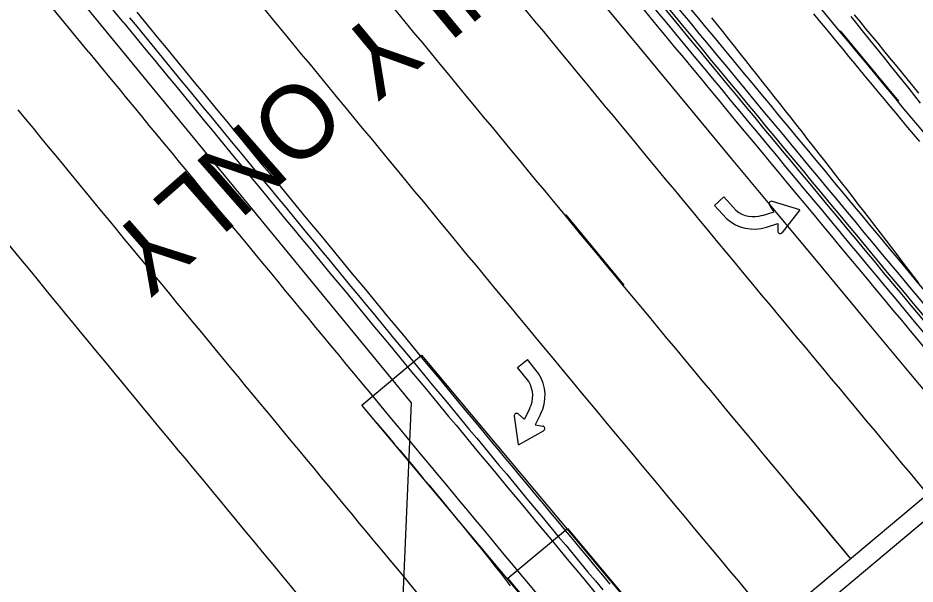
# Model space of a CAD drawing. Extents: x 2252205 to 2259955, y 13788514 to 13798103.
# Drawn here: x 2256222.6 to 2256320.8, y 13792305 to 13792366.9 of the extents above; entities that cross this region are included whole.
import ezdxf

# ---------------------------------------------------------------- set-up
doc = ezdxf.new("R2010")
doc.units = 0
for name, color, linetype in [('D_RDWY_TRACK_BUS', 7, 'Continuous'), ('D_RDWY_TRACK_TRUCK_WB62', 7, 'Continuous'), ('GEOM_CENTERLINE_ALIGN', 7, 'Continuous'), ('ROAD_BIKE_SHARED_USE', 7, 'Continuous'), ('Road_Curb_Back', 7, 'Continuous'), ('Road_Curb_Face', 7, 'Continuous'), ('Road_EdgeOfPavementInside', 7, 'Continuous'), ('Road_EdgeOfPavementOutside', 7, 'Continuous'), ('ROAD_ROW_EXIST', 7, 'Continuous'), ('ROAD_ROW_PROPOSED', 7, 'Continuous'), ('TRAF_PAVMRK_W_24IN_SLD', 7, 'Continuous'), ('TRAF_PAVMRK_W_4IN_BRK', 7, 'Continuous'), ('TRAF_PAVMRK_W_4IN_SLD', 7, 'Continuous'), ('TRAF_PAVMRK_W_8IN_SLD', 7, 'Continuous'), ('TRAF_PAVMRK_W_LT_TRN_ARROW_WORD', 7, 'Continuous'), ('TRAF_PAVMRK_W_RT_TRN_ARROW_WORD', 7, 'Continuous'), ('TRAF_PAVMRK_Y_4IN_SLD', 7, 'Continuous')]:
    doc.layers.add(name, color=color, linetype=linetype)

msp = doc.modelspace()

# ---------------------------------------------------------------- linework, layer by layer
at = {"layer": 'D_RDWY_TRACK_BUS'}
for points in [[(2256321.301, 13792353.365), (2256320.652, 13792354.142), (2256320.003, 13792354.919), (2256319.355, 13792355.695), (2256318.708, 13792356.472), (2256318.062, 13792357.249), (2256317.416, 13792358.026), (2256316.77, 13792358.802), (2256316.125, 13792359.579), (2256315.481, 13792360.356), (2256314.837, 13792361.132), (2256314.194, 13792361.909), (2256313.552, 13792362.686), (2256312.909, 13792363.462), (2256312.268, 13792364.239), (2256311.626, 13792365.015), (2256310.986, 13792365.792), (2256310.345, 13792366.569), (2256309.705, 13792367.345)], [(2256321.403, 13792357.579), (2256320.768, 13792358.373), (2256320.133, 13792359.165), (2256319.498, 13792359.958), (2256318.863, 13792360.749), (2256318.227, 13792361.539), (2256317.592, 13792362.329), (2256316.957, 13792363.118), (2256316.321, 13792363.906), (2256315.686, 13792364.693), (2256315.05, 13792365.48), (2256314.414, 13792366.266), (2256313.779, 13792367.051)], [(2256321.231, 13792337.838), (2256320.631, 13792338.631), (2256320.03, 13792339.423), (2256319.429, 13792340.215), (2256318.826, 13792341.007), (2256318.222, 13792341.797), (2256317.617, 13792342.588), (2256317.011, 13792343.378), (2256316.405, 13792344.167), (2256315.797, 13792344.956), (2256315.189, 13792345.745), (2256314.58, 13792346.533), (2256313.97, 13792347.32), (2256313.359, 13792348.108), (2256312.748, 13792348.895), (2256312.136, 13792349.681), (2256311.523, 13792350.468), (2256310.91, 13792351.254), (2256310.296, 13792352.039), (2256309.681, 13792352.824), (2256309.066, 13792353.609), (2256308.451, 13792354.394), (2256307.834, 13792355.178), (2256307.218, 13792355.963), (2256306.601, 13792356.746), (2256305.983, 13792357.53), (2256305.365, 13792358.313), (2256304.746, 13792359.096), (2256304.127, 13792359.879), (2256303.508, 13792360.662), (2256302.888, 13792361.444), (2256302.268, 13792362.227), (2256301.648, 13792363.009), (2256301.027, 13792363.791), (2256300.406, 13792364.572), (2256299.785, 13792365.354), (2256299.163, 13792366.135), (2256298.541, 13792366.916)], [(2256307.791, 13792281.165), (2256311.646, 13792276.566), (2256305.131, 13792271.106), (2256276.224, 13792305.593), (2256282.738, 13792311.054), (2256307.791, 13792281.165)]]:
    msp.add_lwpolyline(points, dxfattribs=at)
at = {"layer": 'D_RDWY_TRACK_TRUCK_WB62'}
for points in [[(2256321.207, 13792358.664), (2256320.568, 13792359.445), (2256319.929, 13792360.225), (2256319.29, 13792361.005), (2256318.651, 13792361.785), (2256318.012, 13792362.564), (2256317.373, 13792363.342), (2256316.735, 13792364.121), (2256316.096, 13792364.898), (2256315.457, 13792365.676), (2256314.818, 13792366.453), (2256314.179, 13792367.229)], [(2256308.191, 13792280.564), (2256310.761, 13792277.498), (2256304.248, 13792272.037), (2256260.237, 13792324.528), (2256266.75, 13792329.989), (2256308.191, 13792280.564)], [(2256261.843, 13792322.612), (2256262.485, 13792321.846), (2256263.127, 13792321.08), (2256263.768, 13792320.315), (2256264.408, 13792319.552), (2256265.047, 13792318.79), (2256265.683, 13792318.03), (2256266.317, 13792317.272), (2256266.948, 13792316.516), (2256267.577, 13792315.763), (2256268.202, 13792315.012), (2256268.824, 13792314.264), (2256269.442, 13792313.518), (2256270.056, 13792312.775), (2256270.666, 13792312.034), (2256271.271, 13792311.297), (2256271.871, 13792310.561), (2256272.466, 13792309.829), (2256273.056, 13792309.099), (2256273.641, 13792308.371), (2256274.219, 13792307.647), (2256274.792, 13792306.924), (2256275.358, 13792306.205), (2256275.918, 13792305.487), (2256276.472, 13792304.772)]]:
    msp.add_lwpolyline(points, dxfattribs=at)
at = {"layer": 'GEOM_CENTERLINE_ALIGN'}
msp.add_arc((2265118.999, 13799669.27), 11459.16, 219.4185534, 224.3273853, dxfattribs=at)
at = {"layer": 'ROAD_BIKE_SHARED_USE'}
msp.add_line((2256230.297, 13792363.186), (2256103.519, 13792517.426), dxfattribs=at)
for radius, end in [(11505.993, 219.8337025), (11515.993, 219.8337803)]:
    msp.add_arc((2265118.999, 13799669.27), radius, 219.4185534, end, dxfattribs=at)
at = {"layer": 'Road_Curb_Back'}
msp.add_line((2256234.159, 13792366.361), (2256107.555, 13792520.389), dxfattribs=at)
for radius, end in [(11454.327, 219.921869), (11453.993, 219.921869), (11500.993, 219.8232636)]:
    msp.add_arc((2265118.999, 13799669.27), radius, 219.4185534, end, dxfattribs=at)
at = {"layer": 'Road_Curb_Face'}
msp.add_arc((2265118.999, 13799669.27), 11500.16, 219.4185534, 219.8232636, dxfattribs=at)
at = {"layer": 'Road_EdgeOfPavementInside'}
for radius in [11453.16, 11455.16]:
    msp.add_arc((2265118.999, 13799669.27), radius, 219.4185534, 219.921869, dxfattribs=at)
at = {"layer": 'Road_EdgeOfPavementOutside'}
msp.add_arc((2265118.999, 13799669.27), 11500.16, 219.4185534, 219.8232636, dxfattribs=at)
at = {"layer": 'ROAD_ROW_EXIST'}
for p, q in [((2256265.673, 13792324.773), (2256010.405, 13792635.338)), ((2256260.792, 13792213.5), (2256265.673, 13792324.773))]:
    msp.add_line(p, q, dxfattribs=at)
at = {"layer": 'ROAD_ROW_PROPOSED'}
msp.add_arc((2265116.017, 13799666.597), 11522.16, 219.4185534, 219.8015342, dxfattribs=at)
at = {"layer": 'TRAF_PAVMRK_W_24IN_SLD'}
for p, q in [((2256329.829, 13792321.201), (2256295.321, 13792292.32)), ((2256296.15, 13792290.406), (2256331.113, 13792319.667))]:
    msp.add_line(p, q, dxfattribs=at)
at = {"layer": 'TRAF_PAVMRK_W_4IN_BRK'}
for points in [[(2256319, 13792357.789), (2256312.616, 13792365.486)], [(2256319.006, 13792357.781), (2256319, 13792357.789)], [(2256282.535, 13792345.348), (2256282.542, 13792345.341)], [(2256282.542, 13792345.341), (2256288.924, 13792337.642)], [(2256308.07, 13792314.546), (2256308.076, 13792314.538)], [(2256308.076, 13792314.538), (2256313.725, 13792307.723)]]:
    msp.add_lwpolyline(points, dxfattribs=at)
for radius, end in [(11441.16, 219.921869), (11477.16, 219.8969182)]:
    msp.add_arc((2265118.999, 13799669.27), radius, 219.4185534, end, dxfattribs=at)
at = {"layer": 'TRAF_PAVMRK_W_4IN_SLD'}
msp.add_arc((2265118.999, 13799669.27), 11499.16, 219.4185534, 219.8232636, dxfattribs=at)
at = {"layer": 'TRAF_PAVMRK_W_8IN_SLD'}
for radius, end in [(11466.16, 219.8968895), (11488.16, 219.8969469)]:
    msp.add_arc((2265118.999, 13799669.27), radius, 219.4185534, end, dxfattribs=at)
at = {"layer": 'TRAF_PAVMRK_W_LT_TRN_ARROW_WORD'}
for p, q in [((2256299.859, 13792347.318), (2256298.834, 13792346.379)), ((2256300.152, 13792344.94), (2256298.834, 13792346.379)), ((2256301.175, 13792345.852), (2256299.859, 13792347.318)), ((2256299.859, 13792347.318), (2256299.859, 13792347.318)), ((2256305.342, 13792345.711), (2256304.879, 13792346.394)), ((2256308.179, 13792345.882), (2256305.181, 13792346.809)), ((2256304.081, 13792345.28), (2256305.362, 13792345.688)), ((2256308.193, 13792345.881), (2256306.237, 13792343.413)), ((2256304.511, 13792344.004), (2256305.756, 13792344.409)), ((2256305.756, 13792344.409), (2256305.761, 13792343.571))]:
    msp.add_line(p, q, dxfattribs=at)
for centre, radius, start, end in [((2256305.095, 13792346.561), 0.274, 72.80028, 215.06335), ((2256303.131, 13792348.207), 3.06, 230.36726, 288.14805), ((2256303.131, 13792348.207), 4.419, 227.61601, 288.19323), ((2256306.026, 13792343.576), 0.274, 179.73814, 322.00121)]:
    msp.add_arc(centre, radius, start, end, dxfattribs=at)
at = {"layer": 'TRAF_PAVMRK_W_RT_TRN_ARROW_WORD'}
for p, q in [((2256277.264, 13792328.651), (2256278.354, 13792329.514)), ((2256279.566, 13792327.985), (2256278.354, 13792329.514)), ((2256278.504, 13792327.119), (2256277.264, 13792328.651)), ((2256277.264, 13792328.651), (2256277.264, 13792328.651)), ((2256278.609, 13792324.16), (2256278.003, 13792322.96)), ((2256277.365, 13792320.208), (2256276.924, 13792323.315)), ((2256277.983, 13792322.982), (2256277.383, 13792323.548)), ((2256279.8, 13792323.533), (2256279.204, 13792322.367)), ((2256279.204, 13792322.367), (2256280.03, 13792322.231)), ((2256277.364, 13792320.194), (2256280.111, 13792321.735))]:
    msp.add_line(p, q, dxfattribs=at)
for centre, radius, start, end in [((2256275.868, 13792325.56), 4.419, 332.70299, 33.28021), ((2256275.868, 13792325.56), 3.06, 332.74817, 30.52896), ((2256277.184, 13792323.361), 0.274, 45.83287, 188.09595), ((2256279.983, 13792321.97), 0.274, 298.89501, 81.15808)]:
    msp.add_arc(centre, radius, start, end, dxfattribs=at)
at = {"layer": 'TRAF_PAVMRK_Y_4IN_SLD'}
for radius, end in [(11452.16, 219.921869), (11456.16, 219.8968633)]:
    msp.add_arc((2265118.999, 13799669.27), radius, 219.4185534, end, dxfattribs=at)

# ---------------------------------------------------------------- texts
at = {"layer": 'TRAF_PAVMRK_W_LT_TRN_ARROW_WORD'}
msp.add_text('ONLY', height=8, rotation=219.65869, dxfattribs=at).set_placement((2256279.177, 13792382.317))
at = {"layer": 'TRAF_PAVMRK_W_RT_TRN_ARROW_WORD'}
msp.add_text('ONLY', height=8, rotation=221.23753, dxfattribs=at).set_placement((2256253.632, 13792361.319))

doc.saveas('drawing.dxf')
